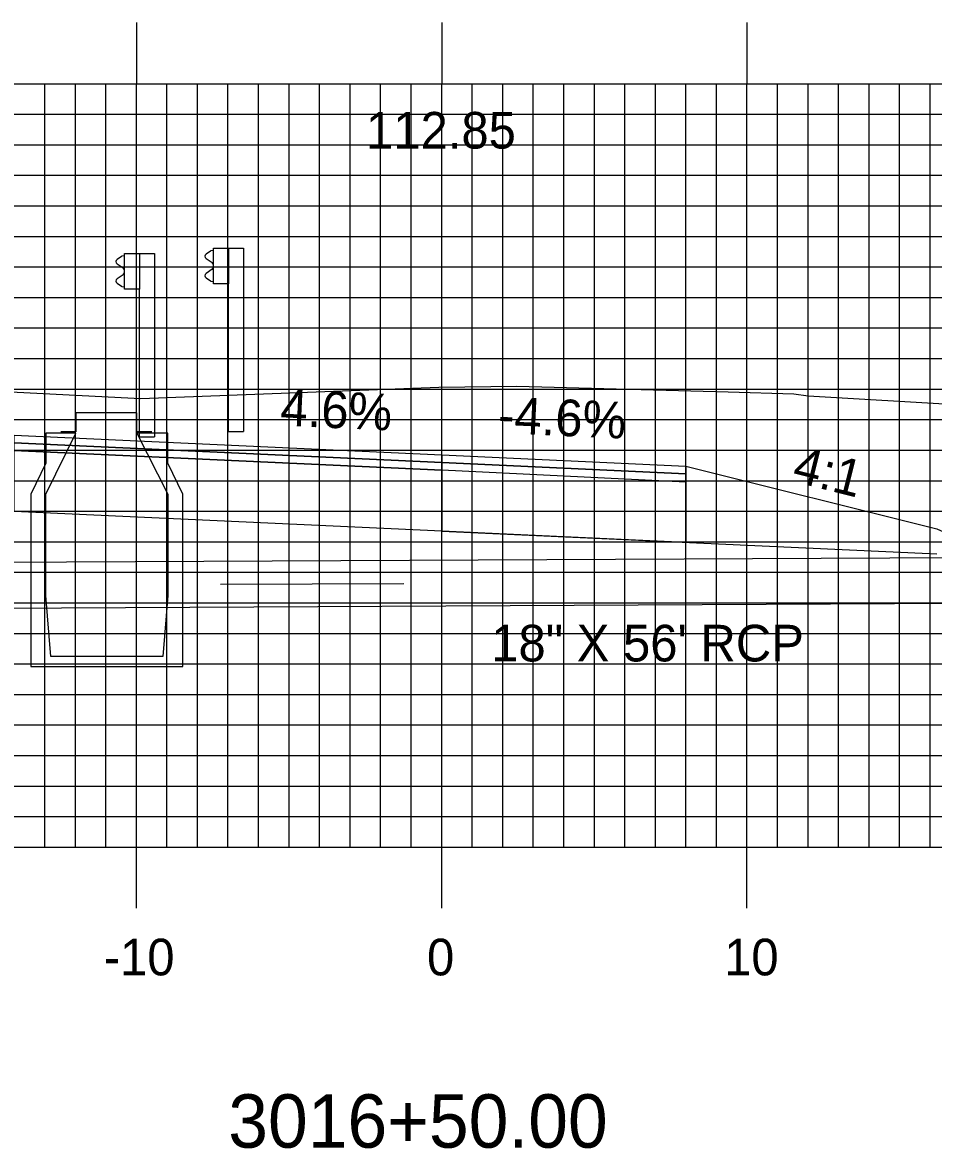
# Model space of a CAD drawing. Extents: x 1685192 to 1685536, y 461260 to 461480.
# Drawn here: x 1685344.5 to 1685374.34, y 461415.34 to 461452.21 of the extents above; entities that cross this region are included whole.
import ezdxf

# ---------------------------------------------------------------- set-up
doc = ezdxf.new("R2010")
doc.units = 0
for name, color, linetype in [('ANNOTATION', 7, 'Continuous'), ('D_Drainage_Culvert', 7, 'Continuous'), ('D_Drainage_Text', 7, 'Continuous'), ('D_Roadway_Centerline_Text', 7, 'Continuous'), ('D_Roadway_Edge_Shoulder', 7, 'Continuous'), ('D_Roadway_Edge_TW', 7, 'Continuous'), ('D_Roadway_Pavement', 7, 'Continuous'), ('D_Roadway_SlopeLines', 7, 'Continuous'), ('D_Roadway_SubGrade', 7, 'Continuous'), ('H_V ANNOTATION', 7, 'Continuous'), ('M_Drainage_CB', 7, 'Continuous'), ('M_Guardrail', 7, 'Continuous'), ('M_Roadway_Centerline', 7, 'Continuous'), ('MAJOR', 7, 'Continuous'), ('MINOR', 7, 'Continuous'), ('S_Roadway_Centerline', 7, 'Continuous')]:
    doc.layers.add(name, color=color, linetype=linetype)

msp = doc.modelspace()

# ---------------------------------------------------------------- linework, layer by layer
at = {"layer": 'D_Drainage_Culvert'}
for p, q in [((1685323.713, 461434.435), (1685379.832, 461434.716)), ((1685356.986, 461433.831), (1685350.986, 461433.801)), ((1685323.713, 461432.935), (1685379.839, 461433.216))]:
    msp.add_line(p, q, dxfattribs=at)
at = {"layer": 'D_Roadway_Edge_Shoulder'}
for points in [[(1685358.229, 461438.051), (1685366.229, 461437.683), (1685366.229, 461437.433), (1685358.229, 461437.801)], [(1685358.229, 461437.801), (1685366.229, 461437.433), (1685366.229, 461437.16), (1685358.229, 461437.551)]]:
    msp.add_lwpolyline(points, close=True, dxfattribs=at)
at = {"layer": 'D_Roadway_Edge_TW'}
msp.add_lwpolyline([(1685344.229, 461438.695), (1685358.229, 461438.051), (1685358.229, 461437.801), (1685344.229, 461438.445)], close=True, dxfattribs=at)
at = {"layer": 'D_Roadway_Pavement'}
msp.add_lwpolyline([(1685344.229, 461438.445), (1685358.229, 461437.801), (1685358.229, 461437.551), (1685344.229, 461438.195)], close=True, dxfattribs=at)
msp.add_lwpolyline([(1685358.229, 461437.801), (1685358.229, 461437.551)], dxfattribs=at)
msp.add_lwpolyline([(1685358.229, 461437.801), (1685358.229, 461437.551)], dxfattribs=at)
msp.add_lwpolyline([(1685358.229, 461437.801), (1685358.229, 461437.551)], dxfattribs=at)
at = {"layer": 'D_Roadway_SlopeLines'}
msp.add_lwpolyline([(1685366.229, 461437.683), (1685374.445, 461435.632), (1685379.839, 461433.216)], dxfattribs=at)
at = {"layer": 'D_Roadway_SubGrade'}
msp.add_line((1685358.229, 461435.551), (1685374.445, 461434.805), dxfattribs=at)
for points in [[(1685344.229, 461438.195), (1685358.229, 461437.551), (1685358.229, 461435.551), (1685344.229, 461436.195)], [(1685358.229, 461437.551), (1685358.229, 461437.801), (1685366.229, 461437.433), (1685366.229, 461437.683), (1685366.229, 461435.183), (1685358.229, 461435.551)]]:
    msp.add_lwpolyline(points, close=True, dxfattribs=at)
at = {"layer": 'M_Drainage_CB'}
for p, q in [((1685346.245, 461438.766), (1685345.26, 461438.766)), ((1685345.26, 461438.766), (1685345.26, 461437.782)), ((1685345.26, 461436.765), (1685346.245, 461438.766)), ((1685349.263, 461438.766), (1685348.246, 461438.766)), ((1685348.246, 461438.766), (1685349.263, 461436.765)), ((1685349.263, 461437.782), (1685349.263, 461438.766)), ((1685345.26, 461437.782), (1685344.768, 461436.765)), ((1685349.755, 461436.765), (1685349.263, 461437.782)), ((1685344.768, 461436.765), (1685344.768, 461431.122)), ((1685345.26, 461433.451), (1685345.26, 461436.765)), ((1685349.263, 461436.765), (1685349.263, 461433.451)), ((1685349.755, 461431.122), (1685349.755, 461436.765)), ((1685345.425, 461431.45), (1685345.26, 461433.451)), ((1685349.263, 461433.451), (1685349.099, 461431.45)), ((1685349.099, 461431.45), (1685345.425, 461431.45)), ((1685344.768, 461431.122), (1685349.755, 461431.122))]:
    msp.add_line(p, q, dxfattribs=at)
msp.add_lwpolyline([(1685348.738, 461438.808), (1685348.246, 461438.808), (1685348.246, 461439.431), (1685346.245, 461439.431), (1685346.245, 461438.808), (1685345.753, 461438.808)], dxfattribs=at)
at = {"layer": 'M_Guardrail'}
for p, q in [((1685350.656, 461444.726), (1685350.513, 461444.626)), ((1685350.755, 461444.747), (1685350.673, 461444.733)), ((1685350.755, 461444.82), (1685351.245, 461444.82)), ((1685350.755, 461443.653), (1685350.755, 461444.82)), ((1685351.245, 461444.82), (1685351.736, 461444.82)), ((1685351.245, 461444.82), (1685351.245, 461443.653)), ((1685351.736, 461444.82), (1685351.736, 461438.82)), ((1685347.739, 461444.55), (1685347.596, 461444.45)), ((1685347.596, 461444.307), (1685347.791, 461444.171)), ((1685347.838, 461444.572), (1685347.756, 461444.557)), ((1685347.838, 461444.645), (1685348.328, 461444.645)), ((1685347.838, 461443.478), (1685347.838, 461444.645)), ((1685348.328, 461444.645), (1685348.819, 461444.645)), ((1685348.328, 461444.645), (1685348.328, 461443.478)), ((1685348.819, 461444.645), (1685348.819, 461438.645)), ((1685350.513, 461444.483), (1685350.708, 461444.347)), ((1685347.791, 461443.951), (1685347.596, 461443.815)), ((1685347.825, 461444.107), (1685347.825, 461444.016)), ((1685350.708, 461444.127), (1685350.513, 461443.991)), ((1685350.742, 461444.282), (1685350.742, 461444.191)), ((1685347.596, 461443.672), (1685347.739, 461443.572)), ((1685347.756, 461443.565), (1685347.838, 461443.551)), ((1685350.513, 461443.847), (1685350.656, 461443.747)), ((1685350.673, 461443.741), (1685350.755, 461443.726)), ((1685351.245, 461443.653), (1685350.755, 461443.653)), ((1685351.245, 461438.82), (1685351.245, 461443.653)), ((1685348.328, 461443.478), (1685347.838, 461443.478)), ((1685348.328, 461438.645), (1685348.328, 461443.478)), ((1685351.245, 461438.82), (1685351.736, 461438.82)), ((1685348.328, 461438.645), (1685348.819, 461438.645))]:
    msp.add_line(p, q, dxfattribs=at)
for centre, major_axis, start_param, end_param in [((1685350.68, 461444.692), (-0.0417, 0), 4.886922, 5.323254), ((1685347.646, 461444.379), (-0.0877, 0), 5.323254, 7.243116), ((1685347.763, 461444.516), (-0.0417, 0), 4.886922, 5.323254), ((1685350.563, 461444.554), (-0.0877, 0), 5.323254, 7.243116), ((1685350.663, 461444.282), (0.0789, 0), 0, 0.959931), ((1685347.746, 461444.107), (0.0789, 0), 0, 0.959931), ((1685347.746, 461444.016), (0.0789, 0), 5.323254, 6.283185), ((1685350.563, 461443.919), (-0.0877, 0), 5.323254, 7.243116), ((1685350.663, 461444.191), (0.0789, 0), 5.323254, 6.283185), ((1685347.646, 461443.744), (-0.0877, 0), 5.323254, 7.243116), ((1685347.763, 461443.606), (-0.0417, 0), 0.959931, 1.396263), ((1685350.68, 461443.781), (-0.0417, 0), 0.959931, 1.396263)]:
    msp.add_ellipse(centre, major_axis=major_axis, ratio=0.995501, start_param=start_param, end_param=end_param, dxfattribs=at)
at = {"layer": 'MAJOR'}
for p, q in [((1685348.229, 461452.21), (1685348.229, 461450.206)), ((1685358.229, 461452.21), (1685358.229, 461450.206)), ((1685368.229, 461452.21), (1685368.229, 461450.206)), ((1685218.229, 461450.206), (1685498.229, 461450.206)), ((1685218.229, 461450.206), (1685498.229, 461450.206)), ((1685348.229, 461425.206), (1685348.229, 461450.206)), ((1685358.229, 461425.206), (1685358.229, 461450.206)), ((1685368.229, 461425.206), (1685368.229, 461450.206)), ((1685218.229, 461445.206), (1685498.229, 461445.206)), ((1685218.229, 461440.206), (1685498.229, 461440.206)), ((1685218.229, 461435.206), (1685498.229, 461435.206)), ((1685218.229, 461430.206), (1685498.229, 461430.206)), ((1685218.229, 461425.206), (1685498.229, 461425.206)), ((1685218.229, 461425.206), (1685498.229, 461425.206)), ((1685348.229, 461423.202), (1685348.229, 461425.206)), ((1685358.229, 461423.202), (1685358.229, 461425.206)), ((1685368.229, 461423.202), (1685368.229, 461425.206))]:
    msp.add_line(p, q, dxfattribs=at)
at = {"layer": 'MINOR'}
for p, q in [((1685345.229, 461425.206), (1685345.229, 461450.206)), ((1685346.229, 461425.206), (1685346.229, 461450.206)), ((1685347.229, 461425.206), (1685347.229, 461450.206)), ((1685349.229, 461425.206), (1685349.229, 461450.206)), ((1685350.229, 461425.206), (1685350.229, 461450.206)), ((1685351.229, 461425.206), (1685351.229, 461450.206)), ((1685352.229, 461425.206), (1685352.229, 461450.206)), ((1685353.229, 461425.206), (1685353.229, 461450.206)), ((1685354.229, 461425.206), (1685354.229, 461450.206)), ((1685355.229, 461425.206), (1685355.229, 461450.206)), ((1685356.229, 461425.206), (1685356.229, 461450.206)), ((1685357.229, 461425.206), (1685357.229, 461450.206)), ((1685359.229, 461425.206), (1685359.229, 461450.206)), ((1685360.229, 461425.206), (1685360.229, 461450.206)), ((1685361.229, 461425.206), (1685361.229, 461450.206)), ((1685362.229, 461425.206), (1685362.229, 461450.206)), ((1685363.229, 461425.206), (1685363.229, 461450.206)), ((1685364.229, 461425.206), (1685364.229, 461450.206)), ((1685365.229, 461425.206), (1685365.229, 461450.206)), ((1685366.229, 461425.206), (1685366.229, 461450.206)), ((1685367.229, 461425.206), (1685367.229, 461450.206)), ((1685369.229, 461425.206), (1685369.229, 461450.206)), ((1685370.229, 461425.206), (1685370.229, 461450.206)), ((1685371.229, 461425.206), (1685371.229, 461450.206)), ((1685372.229, 461425.206), (1685372.229, 461450.206)), ((1685373.229, 461425.206), (1685373.229, 461450.206)), ((1685374.229, 461425.206), (1685374.229, 461450.206)), ((1685218.229, 461449.206), (1685498.229, 461449.206)), ((1685218.229, 461448.206), (1685498.229, 461448.206)), ((1685218.229, 461447.206), (1685498.229, 461447.206)), ((1685218.229, 461446.206), (1685498.229, 461446.206)), ((1685218.229, 461444.206), (1685498.229, 461444.206)), ((1685218.229, 461443.206), (1685498.229, 461443.206)), ((1685218.229, 461442.206), (1685498.229, 461442.206)), ((1685218.229, 461441.206), (1685498.229, 461441.206)), ((1685218.229, 461439.206), (1685498.229, 461439.206)), ((1685218.229, 461438.206), (1685498.229, 461438.206)), ((1685218.229, 461437.206), (1685498.229, 461437.206)), ((1685218.229, 461436.206), (1685498.229, 461436.206)), ((1685218.229, 461434.206), (1685498.229, 461434.206)), ((1685218.229, 461433.206), (1685498.229, 461433.206)), ((1685218.229, 461432.206), (1685498.229, 461432.206)), ((1685218.229, 461431.206), (1685498.229, 461431.206)), ((1685218.229, 461429.206), (1685498.229, 461429.206)), ((1685218.229, 461428.206), (1685498.229, 461428.206)), ((1685218.229, 461427.206), (1685498.229, 461427.206)), ((1685218.229, 461426.206), (1685498.229, 461426.206))]:
    msp.add_line(p, q, dxfattribs=at)
at = {"layer": 'S_Roadway_Centerline'}
msp.add_lwpolyline([(1685286.43, 461435.332), (1685288.431, 461435.437), (1685289.361, 461435.639), (1685289.912, 461435.758), (1685306.542, 461439.532), (1685306.637, 461439.548), (1685308.936, 461439.765), (1685313.647, 461440.214), (1685314.316, 461440.255), (1685330.697, 461440.593), (1685332.454, 461440.571), (1685336.875, 461440.432), (1685338.988, 461440.38), (1685348.379, 461439.9), (1685358.138, 461440.263), (1685360.692, 461440.305), (1685367.617, 461440.119), (1685369.76, 461440.052), (1685370.232, 461439.98), (1685380.088, 461439.409), (1685388.173, 461438.92)], dxfattribs=at)

# ---------------------------------------------------------------- texts
at = {"layer": 'ANNOTATION'}
for s, rotation, p in [('4.6%', 357.3663, (1685352.926, 461439.012)), ('-4.6%', 357.3663, (1685360.055, 461438.769)), ('4:1', 345.9638, (1685369.666, 461437.19))]:
    msp.add_text(s, height=1.2, rotation=rotation, dxfattribs=at).set_placement(p)
at = {"layer": 'D_Drainage_Text'}
msp.add_text('18" X 56\' RCP', height=1.2, dxfattribs=at).set_placement((1685359.851, 461431.286))
at = {"layer": 'D_Roadway_Centerline_Text'}
msp.add_text('112.85', height=1.2, dxfattribs=at).set_placement((1685355.752, 461448.081))
at = {"layer": 'H_V ANNOTATION'}
for s, height, p in [('-10', 1.2, (1685347.159, 461421.006)), ('0', 1.2, (1685357.748, 461421.006)), ('10', 1.2, (1685367.48, 461421.006)), ('3016+50.00', 1.75, (1685351.238, 461415.362))]:
    msp.add_text(s, height=height, dxfattribs=at).set_placement(p)
at = {"layer": 'M_Roadway_Centerline'}
for s, p in [('C', (1685369.755, 461440.052)), ('L', (1685369.76, 461440.045))]:
    msp.add_text(s, height=0.0146, dxfattribs=at).set_placement(p)

doc.saveas('drawing.dxf')
